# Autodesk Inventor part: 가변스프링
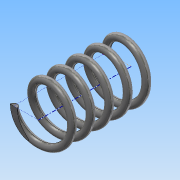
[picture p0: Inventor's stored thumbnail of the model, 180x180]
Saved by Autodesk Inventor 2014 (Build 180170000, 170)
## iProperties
Created: 2019-10
Part Number: 가변스프링
Material: 스테인레스 스틸
Document SubType Name: Modeling
Designer: net
Density: 8.08 g/cm^3
Appearance: 반연마
Mass: 147.867 g
Surface Area: 124.192 cm^2
Volume: 18.3003 cm^3
Author: net
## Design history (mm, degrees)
sketch "스케치1"
  geometry: L1 (0, 0)-(-21, 0); L2 (-21, 0)-(-21, 67.25); L3 (-21, 67.25)-(0, 67.25); L4 (0, 67.25)-(0, 0); C1 r 3 at (-21, 67.25)
  constraints: 8 end point, 2 parallel, 1 centre point, 1 coincident, 1 horizontal, 1 perpendicular
  dimensions: "d0" = 6 diameter of C1; "d1" = 42 diameter of L2 L4; "d2" = 67.25 distance of L3.end L1.start (derived)
feature "코일1" sketch "스케치1" pitch "d3" = 10; turns "d5" = 5; dims "d4" = 67.25 (= d2), "d6" = 0, angle "d7" = 90 deg, angle "d8" = 90 deg, "d9" = 0, "d10" = 0
node "작업 평면1"
sketch "스케치2"
  geometry: L1 (3, 0)-(-3, 0) reference; 1 further point
  constraints: 1 horizontal alignment
extrude "돌출1" cut sketch "스케치2" distance "d11" = 10; taper "d12" = 0 deg
sketch "스케치3"
  geometry: L1 (18, 0)-(24, 0) reference; 1 further point
  constraints: 1 horizontal alignment
extrude "돌출2" cut sketch "스케치3" distance "d13" = 10; taper "d14" = 0 deg
node "솔리드1"
node "절단 모서리 투영1"
node "절단 모서리 투영2"
